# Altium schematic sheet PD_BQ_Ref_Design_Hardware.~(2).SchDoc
size 431 x 279 mm; Date: Not shown in title block; ApprovedBy: Not shown in title block; CheckedBy: Not shown in title block; Author: Not shown in title block; CompanyName: Not shown in title block; Engineer: Not shown in title block; Organization: Not shown in title block; Address1: Not shown in title block; Address2: Not shown in title block; Address3: Not shown in title block; Address4: Not shown in title block; DocumentNumber: 1; Revision: Use project parameter SCH_Rev; SheetNumber: 1; SheetTotal: 1; PageSetup: Record=PageOptions¦CenterHorizontal=True¦CenterVertical=True¦PrintScale=1.00¦XCorrection=1.00¦YCorrection=1.00¦PrintKind=0¦BorderSize=5000000¦LeftOffset=0¦BottomOffset=0¦Orientation=2¦PaperLength=1000¦PaperWidth=1000¦Scale=100¦PaperSource=15¦PrintQuality=600¦MediaType=1¦DitherType=10¦PaperKind=Letter¦PrintScaleMode=1
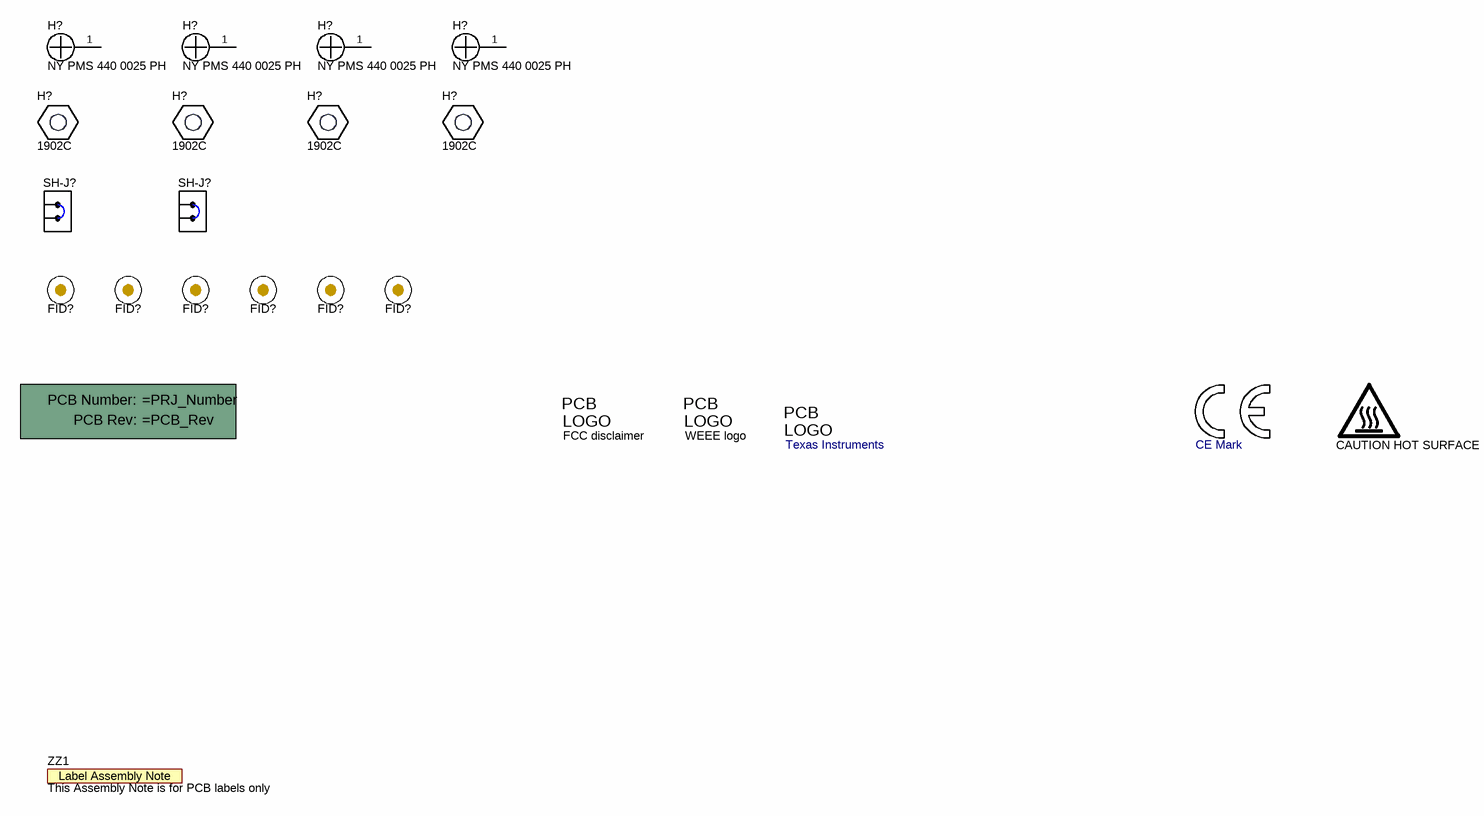
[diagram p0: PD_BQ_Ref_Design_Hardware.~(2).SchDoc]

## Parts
(Parts that share a designator on the sheet are numbered #1, #2 ... from top to bottom, then left to right.)
!PCB1  Printed Circuit Board  (value not drawn)  (mechanical)
FID?#1  Fiducial  [Fiducial10-20]  (value not drawn)
FID?#2  Fiducial  [Fiducial10-20]  (value not drawn)
FID?#3  Fiducial  [Fiducial10-20]  (value not drawn)
FID?#4  Fiducial  [Fiducial10-20]  (value not drawn)
FID?#5  Fiducial  [Fiducial10-20]  (value not drawn)
FID?#6  Fiducial  [Fiducial10-20]  (value not drawn)
H?#1  NY PMS 440 0025 PH  [NY PMS 440 0025 PH]
H?#2  NY PMS 440 0025 PH  [NY PMS 440 0025 PH]
H?#3  NY PMS 440 0025 PH  [NY PMS 440 0025 PH]
H?#4  NY PMS 440 0025 PH  [NY PMS 440 0025 PH]
H?#5  1902C  [Keystone_1902C]
H?#6  1902C  [Keystone_1902C]
H?#7  1902C  [Keystone_1902C]
H?#8  1902C  [Keystone_1902C]
Logo1  CE Mark  [CE_Mark_5mm]  (no BOM)
Logo2  Texas Instruments  [TI_Horizontal_Overlay_Small]  (no BOM)
Logo3  FCC disclaimer  [FCC_disclaimer]  (no BOM)
Logo4  WEEE logo  [WEEE_Minimum]  (no BOM)
LOGO5  CAUTION HOT SURFACE  [IEC_HotSurface_Small]  (no BOM)
SH-J?#1  SNT-100-BK-G  [SNT-100-BK-G]  (value not drawn)
SH-J?#2  SNT-100-BK-G  [SNT-100-BK-G]  (value not drawn)
ZZ1  This Assembly Note is for PCB labels only  [AssemblyNoteLabel]  (no BOM)

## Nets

Not connected (* = marked no-connect by the designer): H?#1 1; H?#2 1; H?#3 1; H?#4 1

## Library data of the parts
!PCB1 = CMP-0003618-2: Manufacturer: Any
FID?#1-FID?#6 = CMP-0077181-1: Fiducial mark.  There is nothing to buy or mount.
H?#1-H?#4 = CMP-0003617-1: Machine Screw, Round, #4-40 x 1/4, Nylon, Philips panhead; Manufacturer: B&F Fastener Supply; CompType: Hardware
H?#5-H?#8 = CMP-0003610-1: Standoff, Hex, 0.5"L #4-40 Nylon; Manufacturer: Keystone; CompType: Hardware
Logo1 = CMP-0074844-1: SymbolCreator: a0412235
Logo2 = CMP-0074838-1: Texas Instrument Corporate Signature; SymbolCreator: a0412235; Lib Reference: TI_Logo
Logo3 = CMP-0074847-1: FCC_disclaimer; Library Reference: Logo
Logo4 = CMP-0074769-1
LOGO5 = CMP-0074837-1: IEC 61010-1 Hot Surface Warning; SymbolCreator: a0412235
SH-J?#1 SH-J?#2 = CMP-0003623-1: Shunt, 100mil, Gold plated, Black; Alternate PartNumber: 969102-0000-DA; Manufacturer: Samtec; Alternate Manufacturer: 3M; Value: 1x2; Note: You can "mate" this to a header by matching the designator.  i.e. use SH-J3 for header J3
ZZ1 = CMP-0003616-3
